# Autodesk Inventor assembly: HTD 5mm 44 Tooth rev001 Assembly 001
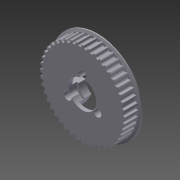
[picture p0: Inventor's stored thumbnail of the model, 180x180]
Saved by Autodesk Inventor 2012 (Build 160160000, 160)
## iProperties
Created: 2012-12
Part Number: HTD 5mm 44 Tooth rev001 Assembly 001
Document SubType Name: Assembly
Designer: Owner
Author: Owner
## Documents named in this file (4)
- C:\Users\Owner\Documents\Robotics\Mechanical Design\Parts\pulley\HTD\44\HTD 5mm 44 Tooth rev001 Assembly 001.iam
- C:\Users\Owner\Documents\Robotics\Mechanical Design\Parts\pulley\HTD\44\HTD 5mm 44 Tooth rev001 step 3.ipt
- C:\Users\Owner\Documents\Robotics\Mechanical Design\Parts\pulley\HTD\44\HTD 5mm 44 Tooth Flange_rev001.ipt
- C:\Users\Owner\Documents\Robotics\Mechanical Design\Parts\pulley\HTD\44\step.ipt
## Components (3 placed, 3 different names)
1. HTD 5mm 44 Tooth rev001 step 3:1 — Mate:1, Mate:2, Mate:3, Flush:1, Flush:2, Flush:3, Mate:4, Mate:5, Mate:6
2. HTD 5mm 44 Tooth Flange_rev001:1 — Mate:1, Mate:2, Mate:3
3. step:1 — Flush:3, Mate:4, Mate:5, Mate:6
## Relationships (9: Mate 6, Flush 3)
- Mate:1: HTD 5mm 44 Tooth rev001 step 3:1 ↔ HTD 5mm 44 Tooth Flange_rev001:1
- Mate:2: HTD 5mm 44 Tooth rev001 step 3:1 ↔ HTD 5mm 44 Tooth Flange_rev001:1
- Mate:3: HTD 5mm 44 Tooth rev001 step 3:1 ↔ HTD 5mm 44 Tooth Flange_rev001:1
- Flush:1: HTD 5mm 44 Tooth rev001 step 3:1
- Flush:2: HTD 5mm 44 Tooth rev001 step 3:1
- Flush:3: HTD 5mm 44 Tooth rev001 step 3:1 ↔ step:1
- Mate:4: HTD 5mm 44 Tooth rev001 step 3:1 ↔ step:1
- Mate:5: HTD 5mm 44 Tooth rev001 step 3:1 ↔ step:1
- Mate:6: HTD 5mm 44 Tooth rev001 step 3:1 ↔ step:1
